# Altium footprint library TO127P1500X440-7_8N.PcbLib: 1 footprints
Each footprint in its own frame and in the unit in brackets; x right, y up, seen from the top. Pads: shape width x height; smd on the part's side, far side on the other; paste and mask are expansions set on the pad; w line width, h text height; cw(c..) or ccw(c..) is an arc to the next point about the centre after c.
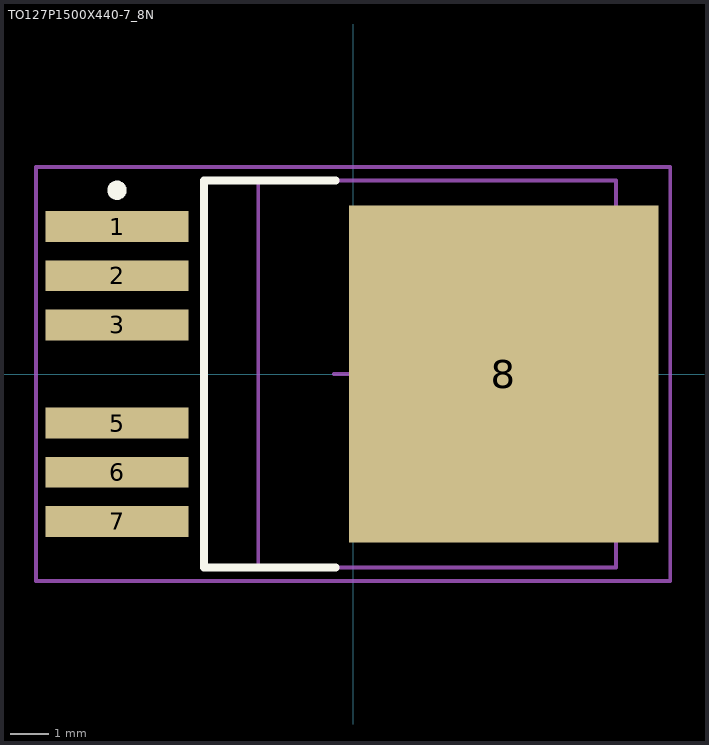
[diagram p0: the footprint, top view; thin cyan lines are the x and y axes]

## TO127P1500X440-7_8N [mm] "TO,1.27mm pitch;7 pin,15.00mm L X 9.25mm W X 4.40mm H body"
height 4.4
pads (7):
  rect 3.7x0.8 smd paste+0 mask+0: 1(-6.1,3.81) 2(-6.1,2.54) 3(-6.1,1.27) 5(-6.1,-1.27) 6(-6.1,-2.54) 7(-6.1,-3.81)
  rect 8x8.7 smd paste+0 mask+0: 8(3.9,0)
Top Overlay:
  circle w0.25: c-6.1,4.75 r0.125
  lines w0.2: -0.45,-5 -3.85,-5 -3.85,5 -0.45,5
Mechanical 13:
  lines w0.1: -2.45,-5 6.8,-5 6.8,5 -2.45,5 -2.45,-5
Mechanical 15:
  lines w0.1: -0.5,0 0.5,0 ; 0,-0.5 0,0.5 ; -8.2,-5.35 8.2,-5.35 8.2,5.35 -8.2,5.35 -8.2,-5.35
3D body: height 4.51, standoff 0, extent -7.475,-4.974 7.475,5.026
